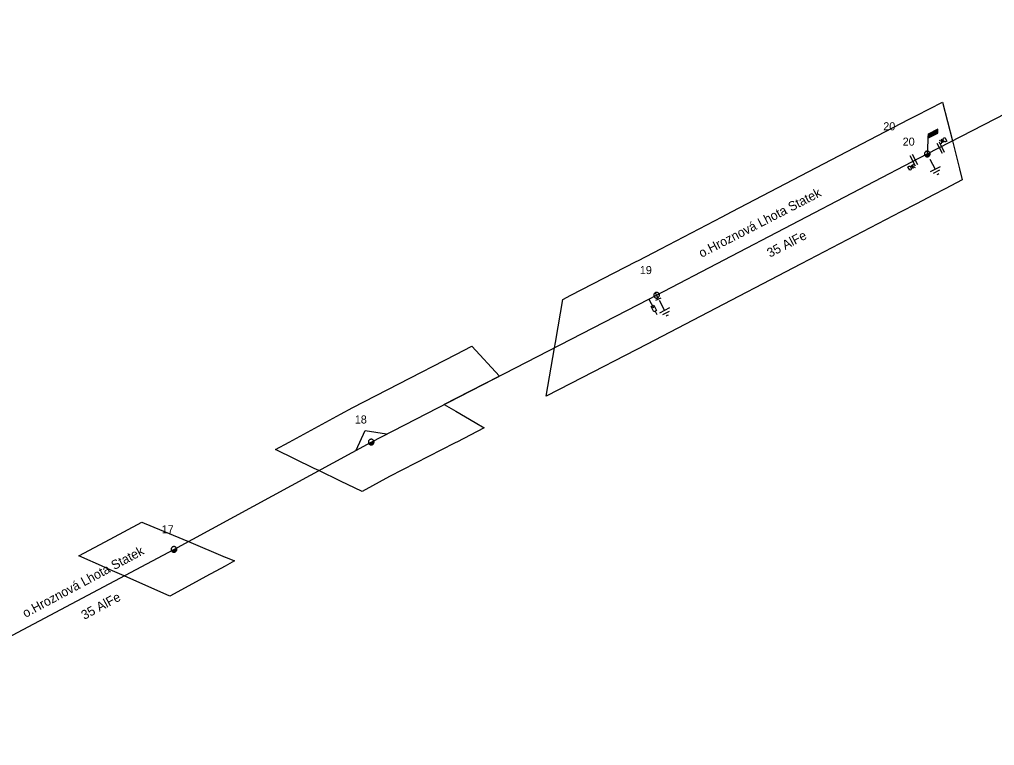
# Model space of a CAD drawing. Extents: x -544790 to -541580, y -1198998 to -1195432.
# Drawn here: x -542232.2 to -542020.6, y -1198828.4 to -1198670.7 of the extents above; entities that cross this region are included whole.
import ezdxf

# ---------------------------------------------------------------- set-up
doc = ezdxf.new("R2010")
doc.units = 0
for name, color, linetype in [('DOPLŇ_POPISY', 7, 'Continuous'), ('ELE_EON_POPIS', 7, 'Continuous'), ('Implicitní', 7, 'Continuous'), ('KN_HRAN_POHYBLIVÁ', 7, 'Continuous'), ('KN_HRAN_STÁTNÍ', 7, 'Continuous'), ('KONEC_VEDENÍ', 7, 'Continuous'), ('PB_NN', 7, 'Continuous'), ('PB_NN_POPIS', 7, 'Continuous'), ('PK_HRAN_SPORNÁ', 7, 'Continuous'), ('PLG_EXPORT_GPE', 7, 'Continuous'), ('PODZEM_NN_POPIS', 7, 'Continuous'), ('RÁMEČEK', 7, 'Continuous'), ('TECH_OCHR_PÁSMO_HRAN', 7, 'Continuous')]:
    doc.layers.add(name, color=color, linetype=linetype)

# ---------------------------------------------------------------- blocks, each defined once
blk = doc.blocks.new('VN850')
at = {"layer": 'RÁMEČEK'}
for points in [[(-0.56, 1.43), (-0.56, -1.07)], [(-0.01, 1.43), (-0.01, -1.07)], [(-2.09, -0.54), (-1.78, -0.54)], [(-2.09, -1.41), (-2.09, -0.54)], [(-1.78, -1.41), (-2.09, -1.41)], [(-1.78, -0.54), (-1.66, -0.6)], [(-1.67, -1.35), (-1.78, -1.41)], [(-1.59, -1.2), (-1.67, -1.35)], [(-1.66, -0.6), (-1.59, -0.75)], [(-1.59, -0.75), (-1.55, -0.96)], [(-1.55, -0.96), (-1.59, -1.2)], [(-1.26, -0.54), (-1.26, -1.41)], [(-0.85, -0.54), (-1.26, -1.09)], [(-1.13, -0.92), (-0.77, -1.41)]]:
    blk.add_lwpolyline(points, dxfattribs=at)
blk = doc.blocks.new('VN860')
at = {"layer": 'RÁMEČEK'}
for points in [[(-3.74, 0), (0.01, 2.82)], [(0.01, 2.82), (3.76, 0)]]:
    blk.add_lwpolyline(points, dxfattribs=at)
blk = doc.blocks.new('VN440')
at = {"layer": 'ELE_EON_POPIS'}
for points in [[(1.22, 0), (1.21, 0.13), (1.19, 0.25), (1.16, 0.38), (1.11, 0.5), (1.05, 0.61), (0.98, 0.72), (0.9, 0.82), (0.81, 0.91), (0.71, 0.99), (0.6, 1.06), (0.49, 1.12), (0.37, 1.16), (0.25, 1.2), (0.12, 1.22), (-0.01, 1.22), (-0.14, 1.22), (-0.26, 1.2), (-0.39, 1.16), (-0.51, 1.12), (-0.62, 1.06), (-0.73, 0.99), (-0.83, 0.91), (-0.92, 0.82), (-1, 0.72), (-1.07, 0.61), (-1.13, 0.5), (-1.18, 0.38), (-1.21, 0.25), (-1.23, 0.13), (-1.24, 0), (-1.23, -0.13), (-1.21, -0.26), (-1.18, -0.38), (-1.13, -0.5), (-1.07, -0.62), (-1, -0.73), (-0.92, -0.83), (-0.83, -0.92), (-0.73, -1), (-0.62, -1.07), (-0.51, -1.13), (-0.39, -1.17), (-0.26, -1.2), (-0.14, -1.23), (-0.01, -1.23), (0.12, -1.23), (0.25, -1.2), (0.37, -1.17), (0.49, -1.13), (0.6, -1.07), (0.71, -1), (0.81, -0.92), (0.9, -0.83), (0.98, -0.73), (1.05, -0.62), (1.11, -0.5), (1.16, -0.38), (1.19, -0.26), (1.21, -0.13), (1.22, 0)], [(-1.24, 0), (1.22, 0)], [(-1.18, -0.34), (1.1, -0.34)], [(-1.01, -0.63), (0.97, -0.63)], [(-0.74, -0.92), (0.68, -0.92)]]:
    blk.add_lwpolyline(points, dxfattribs=at)
blk = doc.blocks.new('VN820')
at = {"layer": 'DOPLŇ_POPISY'}
for points in [[(0, 0), (0, -2.1)], [(-0.32, -1.63), (0.34, -1.63)], [(-0.32, -2.95), (-0.32, -1.63)], [(0, -2.1), (-0.12, -1.86)], [(0, -2.1), (0.12, -1.86)], [(0.34, -1.63), (0.34, -2.95)], [(0.34, -2.95), (-0.32, -2.95)], [(0, -2.95), (0, -3.75)]]:
    blk.add_lwpolyline(points, dxfattribs=at)
blk = doc.blocks.new('VN810')
at = {"layer": 'PLG_EXPORT_GPE'}
for points in [[(0, -1.25), (0, -3.75)], [(1.25, -3.75), (-1.25, -3.75)], [(0.77, -4.37), (-0.8, -4.37)], [(0, -5), (-0.25, -5)], [(0.27, -5), (0, -5)]]:
    blk.add_lwpolyline(points, dxfattribs=at)
blk = doc.blocks.new('VN001')
at = {"layer": 'Implicitní'}
for p, q in [((1.73, 3.03), (4.14, 3.03)), ((1.76, 3.08), (4.17, 3.08)), ((1.79, 3.13), (4.2, 3.13)), ((1.82, 3.18), (4.23, 3.18)), ((1.85, 3.23), (4.26, 3.23)), ((1.87, 3.28), (4.29, 3.28)), ((1.9, 3.33), (4.32, 3.33)), ((1.93, 3.38), (4.35, 3.38)), ((1.96, 3.43), (4.37, 3.43)), ((1.99, 3.48), (4.4, 3.48)), ((2.02, 3.53), (4.43, 3.53)), ((2.05, 3.58), (4.46, 3.58)), ((2.07, 3.63), (4.49, 3.63)), ((2.1, 3.68), (4.52, 3.68)), ((2.13, 3.73), (2.54, 3.73))]:
    blk.add_line(p, q, dxfattribs=at)
blk.add_lwpolyline([(2.13, 3.73), (0, 0)], dxfattribs=at)
blk.add_lwpolyline([(4.55, 3.73), (2.13, 3.73), (1.7, 2.98), (4.12, 2.99)], close=True, dxfattribs=at)
blk = doc.blocks.new('VN410')
at = {"layer": 'ELE_EON_POPIS'}
for points in [[(0, 1.24), (-0.13, 1.23), (-0.25, 1.21), (-0.38, 1.18), (-0.5, 1.13), (-0.61, 1.07), (-0.72, 1), (-0.82, 0.92), (-0.91, 0.83), (-0.99, 0.73), (-1.06, 0.62), (-1.12, 0.51), (-1.17, 0.39), (-1.2, 0.26), (-1.22, 0.14), (-1.23, 0.01), (-1.22, -0.12), (-1.2, -0.25), (-1.17, -0.37), (-1.12, -0.49), (-1.06, -0.61), (-0.99, -0.71), (-0.91, -0.81), (-0.82, -0.91), (-0.72, -0.99), (-0.61, -1.06), (-0.5, -1.11), (-0.38, -1.16), (-0.25, -1.19), (-0.13, -1.21), (0, -1.22), (0.13, -1.21), (0.26, -1.19), (0.38, -1.16), (0.5, -1.11), (0.61, -1.06), (0.72, -0.99), (0.82, -0.91), (0.91, -0.81), (0.99, -0.71), (1.06, -0.61), (1.12, -0.49), (1.17, -0.37), (1.2, -0.25), (1.22, -0.12), (1.23, 0.01), (1.22, 0.14), (1.2, 0.26), (1.17, 0.39), (1.12, 0.51), (1.06, 0.62), (0.99, 0.73), (0.91, 0.83), (0.82, 0.92), (0.72, 1), (0.61, 1.07), (0.5, 1.13), (0.38, 1.18), (0.26, 1.21), (0.13, 1.23), (0, 1.24)], [(-1.23, 0), (1.23, 0)], [(0, -1.23), (0, 1.23)], [(1.86, -1.23), (1.86, 1.23)]]:
    blk.add_lwpolyline(points, dxfattribs=at)

msp = doc.modelspace()

# ---------------------------------------------------------------- linework, layer by layer
at = {"layer": 'PK_HRAN_SPORNÁ'}
for points in [[(-542112.5, -1198749.74), (-542117.88, -1198752.51), (-542116.05, -1198742.01), (-542115.85, -1198740.85), (-542115.27, -1198737.5), (-542114.22, -1198731.51), (-542112.5, -1198730.62), (-542098.31, -1198723.31), (-542097.81, -1198723.05), (-542092.94, -1198720.51), (-542079.63, -1198713.56), (-542077.6, -1198712.5), (-542062.5, -1198704.61), (-542046, -1198696), (-542039.07, -1198692.38), (-542037.5, -1198691.57), (-542031.84, -1198688.65), (-542029.69, -1198697.1), (-542028.15, -1198703.15), (-542027.54, -1198705.56), (-542031.23, -1198707.47), (-542033.81, -1198708.81), (-542037.5, -1198710.74), (-542040.87, -1198712.5), (-542062.5, -1198723.79), (-542084.43, -1198735.24), (-542095.92, -1198741.2)], [(-542133.26, -1198758.26), (-542131.3, -1198759.42), (-542137.28, -1198762.5), (-542137.5, -1198762.61), (-542137.73, -1198762.73), (-542151.85, -1198770), (-542157.81, -1198773.25), (-542162.5, -1198770.98), (-542167.22, -1198768.69), (-542168.21, -1198768.21), (-542176.62, -1198764.14), (-542173.62, -1198762.5), (-542162.5, -1198756.44), (-542159.81, -1198754.98), (-542149.85, -1198749.85), (-542137.5, -1198743.49), (-542133.98, -1198741.68), (-542128, -1198748.16), (-542137.5, -1198753.05), (-542139.97, -1198754.32), (-542137.5, -1198755.77)], [(-542187.48, -1198787.48), (-542187.43, -1198787.5), (-542185.48, -1198788.32), (-542187.5, -1198789.42), (-542191.71, -1198791.71), (-542194.61, -1198793.29), (-542199.57, -1198795.93), (-542209.45, -1198791.56), (-542212.5, -1198790.21), (-542214.38, -1198789.38), (-542218.64, -1198787.5), (-542219.32, -1198787.2), (-542212.5, -1198783.56), (-542205.58, -1198779.87), (-542205.08, -1198780.08), (-542195.51, -1198784.1), (-542187.5, -1198787.47)]]:
    msp.add_lwpolyline(points, close=True, dxfattribs=at)
at = {"layer": 'PODZEM_NN_POPIS'}
for points in [[(-542035.15, -1198699.92), (-541978.5, -1198670.71)], [(-542279.15, -1198828.4), (-542233.66, -1198804.46), (-542198.64, -1198785.81), (-542155.83, -1198762.49), (-542095.54, -1198731.44), (-542093.9, -1198730.6), (-542035.15, -1198699.92)]]:
    msp.add_lwpolyline(points, dxfattribs=at)

# ---------------------------------------------------------------- block references
at = {"layer": 'DOPLŇ_POPISY'}
for name, p, xscale, yscale, rotation in [('VN440', (-542035.15, -1198699.92), 0.49999999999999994, 0.5000000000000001, 27.32115275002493), ('VN410', (-542093.9, -1198730.6), 0.4999999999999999, 0.5, -63.138438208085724), ('VN440', (-542155.83, -1198762.49), 0.5000000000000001, 0.4999999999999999, 28.57839997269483), ('VN440', (-542198.64, -1198785.81), 0.49999999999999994, 0.5000000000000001, 27.25376953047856)]:
    msp.add_blockref(name, p, dxfattribs=dict(at, xscale=xscale, yscale=yscale, rotation=rotation))
at = {"layer": 'KN_HRAN_POHYBLIVÁ'}
for name, p, rotation in [('VN850', (-542032.53, -1198698.57), -152.72376386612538), ('VN850', (-542037.75, -1198701.26), 27.32198332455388), ('VN860', (-542155.83, -1198762.49), 28.578486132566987)]:
    msp.add_blockref(name, p, dxfattribs=dict(at, rotation=rotation))
at = {"layer": 'KN_HRAN_STÁTNÍ', "rotation": 27.24555228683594}
msp.add_blockref('VN820', (-542095.54, -1198731.44), dxfattribs=at)
at = {"layer": 'RÁMEČEK'}
for p, rotation in [((-542035.15, -1198699.92), 27.32152219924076), ((-542093.9, -1198730.6), 27.547483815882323)]:
    msp.add_blockref('VN810', p, dxfattribs=dict(at, rotation=rotation))
at = {"layer": 'TECH_OCHR_PÁSMO_HRAN', "rotation": 27.321224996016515}
msp.add_blockref('VN001', (-542035.15, -1198699.92), dxfattribs=at)

# ---------------------------------------------------------------- texts
at = {"layer": 'KONEC_VEDENÍ'}
msp.add_text('20', height=1.75, dxfattribs=at).set_placement((-542044.69, -1198694.78))
at = {"layer": 'PB_NN'}
for rotation, p in [(27.321, (-542069.3, -1198722.46)), (28.326, (-542218.1, -1198801.14))]:
    msp.add_text('35 AlFe', height=2, rotation=rotation, dxfattribs=at).set_placement(p)
at = {"layer": 'PB_NN_POPIS'}
for rotation, p in [(27.321, (-542084.12, -1198722.49)), (28.326, (-542230.85, -1198800.7))]:
    msp.add_text('o.Hroznová Lhota Statek', height=2, rotation=rotation, dxfattribs=at).set_placement(p)
at = {"layer": 'PLG_EXPORT_GPE'}
for s, p in [('20', (-542040.48, -1198698.12)), ('19', (-542097.53, -1198726.01)), ('18', (-542159.39, -1198758.46)), ('17', (-542201.3, -1198782.31))]:
    msp.add_text(s, height=1.75, dxfattribs=at).set_placement(p)

doc.saveas('drawing.dxf')
